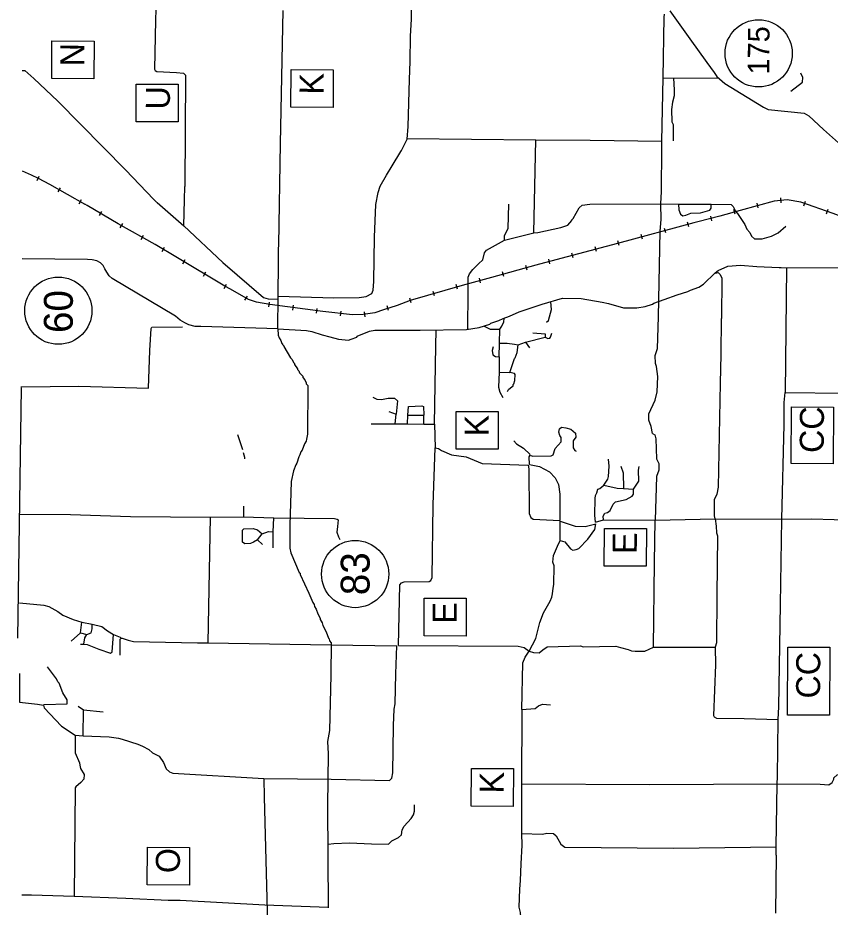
# Model space of a CAD drawing. Extents: x 299354 to 1325680, y 96128 to 228242.
# Drawn here: x 299354 to 333137, y 121656 to 158651 of the extents above; entities that cross this region are included whole.
import ezdxf

# ---------------------------------------------------------------- set-up
doc = ezdxf.new("R2010")
doc.units = 0
for name, color, linetype in [('Level 12', 7, 'Continuous'), ('Level 13', 7, 'Continuous'), ('Level 2', 7, 'Continuous'), ('Level 3', 7, 'Continuous'), ('Level 4', 7, 'Continuous'), ('Level 57', 7, 'Continuous')]:
    doc.layers.add(name, color=color, linetype=linetype)

msp = doc.modelspace()

# ---------------------------------------------------------------- linework, layer by layer
at = {"layer": 'Level 12'}
for p, q in [((330161, 157171), (330161, 157171)), ((301041, 146467), (301041, 146467)), ((313383, 135513), (313383, 135513))]:
    msp.add_line(p, q, dxfattribs=at)
for centre in [(330161, 157171), (301041, 146467), (313383, 135513)]:
    msp.add_circle(centre, 1398, dxfattribs=at)
at = {"layer": 'Level 13'}
for p, q in [((301625, 156936), (301625, 156936)), ((311569, 155744), (311569, 155744)), ((305128, 155140), (305128, 155140)), ((318436, 141524), (318436, 141524)), ((332373, 141333), (332373, 141333)), ((324597, 136657), (324597, 136657)), ((317106, 133756), (317106, 133756)), ((332221, 131118), (332221, 131118)), ((319065, 126671), (319065, 126671)), ((305595, 123397), (305595, 123397))]:
    msp.add_line(p, q, dxfattribs=at)
for points in [[(302519, 156115), (300769, 156122), (300775, 157692), (302525, 157685)], [(312463, 154922), (310713, 154930), (310720, 156499), (312470, 156492)], [(306022, 154319), (304272, 154326), (304278, 155896), (306028, 155889)], [(333265, 140102), (331515, 140109), (331525, 142464), (333275, 142457)], [(319330, 140702), (317580, 140709), (317586, 142279), (319336, 142272)], [(325491, 135835), (323741, 135842), (323747, 137412), (325497, 137405)], [(318000, 132935), (316250, 132942), (316256, 134512), (318006, 134505)], [(333113, 129642), (331363, 129649), (331374, 132475), (333124, 132468)], [(319959, 125850), (318209, 125857), (318215, 127427), (319965, 127420)], [(306489, 122575), (304739, 122582), (304746, 124152), (306496, 124145)]]:
    msp.add_lwpolyline(points, close=True, dxfattribs=at)
at = {"layer": 'Level 2'}
for points in [[(310170, 145708), (310183, 147075), (312501, 147004), (313552, 147011), (313844, 147058), (314079, 147189), (314130, 147322), (314158, 147680), (314192, 149530), (314238, 150880), (314343, 151387), (314428, 151645), (314683, 152101), (314928, 152498), (315276, 153095), (315309, 153128), (315411, 153327), (315547, 153609), (315586, 154134), (315637, 156084), (315677, 156833), (315687, 157883), (315727, 158591), (315765, 160908)], [(305089, 158996), (305085, 158554), (305033, 156521), (305065, 156454), (305132, 156421), (305949, 156380), (306249, 156344), (306331, 156268), (306305, 151635)], [(310275, 153424), (310393, 158948)], [(326463, 158936), (327303, 157778), (328003, 156788), (328308, 156377), (328423, 156210), (328754, 155915), (330363, 154934), (330562, 154832), (332054, 154685), (332253, 154567), (332856, 154003), (333485, 153447), (333932, 153043), (334287, 152715), (334725, 152269), (335006, 151967), (335073, 151862), (335107, 151815), (335153, 151743)], [(299532, 156455), (299644, 156454), (300025, 156125), (301017, 155183), (303843, 152315), (304999, 151105), (305142, 150972)], [(310203, 149208), (310275, 153424)], [(306289, 151078), (306305, 151635)], [(310201, 149032), (310203, 149208)], [(310170, 145708), (306967, 145814), (306725, 145816), (306473, 145883), (306295, 145970), (306107, 146078), (305909, 146240), (303285, 147808), (303149, 147916), (303056, 148076), (302973, 148215), (302901, 148343), (302787, 148461), (302640, 148537), (302441, 148582), (302251, 148595), (299531, 148627)], [(310170, 145708), (311354, 145639), (311579, 145604), (312011, 145466), (312336, 145380), (312693, 145285), (313102, 145248), (313219, 145280), (313453, 145370), (313470, 145403), (313981, 145615), (314206, 145663), (316083, 145663), (318018, 145679), (318544, 145774), (318987, 145911), (319021, 145944), (319364, 146058), (319532, 146140), (319799, 146237), (320210, 146425), (321163, 146733), (322000, 146984), (322775, 146977), (323658, 146819), (323924, 146767), (324548, 146586), (325098, 146581), (325449, 146645), (325742, 146742), (325809, 146783), (326236, 146929), (326780, 147124), (327223, 147262), (327324, 147328), (327675, 147441), (327868, 147573), (328348, 148043), (328482, 148142), (328876, 148314), (329402, 148359), (330093, 148303), (331010, 148269), (331094, 148269), (333771, 148244)], [(331326, 148269), (331262, 143059)], [(310170, 145708), (310185, 145449), (310217, 145333), (310299, 145223), (310332, 145106), (310365, 145090), (310364, 145056), (310414, 145006), (310414, 144972), (310701, 144511), (310767, 144444), (310816, 144310), (310866, 144268), (310866, 144235), (310989, 144050), (310989, 144017), (311038, 143967), (311071, 143883), (311203, 143740), (311202, 143690), (311285, 143589), (311351, 143472), (311350, 143422), (311416, 143355), (311398, 141338), (311362, 141130), (311345, 141047), (311277, 140931), (311175, 140665), (311124, 140591), (311089, 140474), (311039, 140392), (310953, 140126), (310910, 140051), (310825, 139802), (310720, 139361), (310670, 137553), (310662, 136587), (310710, 136394), (311061, 135583), (311094, 135549), (311094, 135499), (311462, 134713), (311625, 134336), (311674, 134252), (311690, 134169), (311756, 134052), (311837, 133859), (311927, 133675), (311927, 133625), (312009, 133491), (312041, 133374), (312172, 133114), (312270, 132847), (312303, 132813), (312319, 132738), (312385, 132654), (312372, 131304), (312318, 129013), (312230, 128555), (312259, 128030), (312239, 125880), (312267, 121630)], [(316689, 141749), (316740, 145000)], [(331131, 137801), (331217, 141734), (331225, 142651), (331262, 143059)], [(316689, 141749), (316705, 140765)], [(316705, 140765), (316855, 140731), (316971, 140646), (317394, 140467), (318002, 140395), (318659, 140106), (320576, 140039)], [(320627, 140071), (321051, 139993), (321458, 139772), (321706, 139520), (321837, 139244), (321891, 138835), (321898, 137735)], [(321907, 136910), (321914, 137718)], [(321914, 137718), (322538, 137512), (322946, 137492), (323398, 137605)], [(323382, 137671), (323708, 137769)], [(323708, 137769), (325859, 137749)], [(325859, 137749), (328353, 137810)], [(328353, 137810), (331131, 137801)], [(330970, 129469), (331008, 129994), (331064, 134252), (331131, 137801)], [(331131, 137801), (332373, 137807)], [(332373, 137807), (333299, 137782), (336317, 137721)], [(320622, 132313), (320902, 132835), (321058, 133492), (321212, 133899), (321491, 134388), (321560, 134555), (321594, 134688), (321613, 134929), (321648, 135079), (321655, 135854), (321607, 136012), (321626, 136279), (321796, 136669), (321907, 136910)], [(312365, 132572), (315119, 132529)], [(315186, 132546), (320165, 132517), (320406, 132465), (320622, 132313)], [(320316, 129874), (320350, 131824), (320452, 132056), (320622, 132313)], [(320316, 129874), (320304, 126791)], [(330929, 126795), (330948, 127086), (330970, 129469)], [(320304, 126791), (320301, 124724)], [(330888, 124170), (330929, 126795)], [(320301, 124724), (320314, 124232), (320273, 123458), (320250, 122774), (320213, 122408), (320190, 121658), (320238, 121441), (320268, 121083), (320316, 120899), (320310, 120199)], [(330885, 123820), (330888, 124170)], [(330885, 123820), (330862, 121406)], [(299516, 122170), (299920, 122167), (301696, 122117)], [(301696, 122117), (303847, 122031)], [(303847, 122031), (305614, 121949)], [(305614, 121949), (306106, 121944), (309624, 121754)], [(309624, 121754), (312267, 121663)]]:
    msp.add_lwpolyline(points, dxfattribs=at)
at = {"layer": 'Level 3'}
for points in [[(305145, 150969), (306257, 150002)], [(306257, 150002), (306289, 151078)], [(306257, 150002), (307886, 148479), (309570, 147018), (309764, 146962), (310183, 146947)], [(310195, 148408), (310201, 149032)], [(310190, 147899), (310195, 148408)], [(310183, 147075), (310188, 147666)], [(310188, 147666), (310190, 147899)], [(316740, 145003), (316750, 145657)]]:
    msp.add_lwpolyline(points, dxfattribs=at)
at = {"layer": 'Level 4'}
for p, q in [((300164, 151885), (300249, 152066)), ((301034, 151408), (301132, 151582)), ((301906, 150917), (302004, 151091)), ((331105, 150958), (331086, 151157)), ((332042, 150829), (332108, 151018)), ((302752, 150422), (302852, 150595)), ((329186, 150479), (329130, 150672)), ((330148, 150746), (330096, 150939)), ((332986, 150499), (333052, 150688)), ((328219, 150212), (328170, 150406)), ((303618, 149921), (303716, 150095)), ((326297, 149700), (326245, 149893)), ((327262, 149960), (327210, 150153)), ((304490, 149430), (304588, 149604)), ((325331, 149440), (325279, 149633)), ((305355, 148933), (305457, 149105)), ((323416, 148928), (323365, 149121)), ((324365, 149180), (324313, 149374)), ((322450, 148671), (322398, 148864)), ((306214, 148422), (306317, 148594)), ((321483, 148414), (321432, 148608)), ((307071, 147908), (307174, 148079)), ((319564, 147889), (319511, 148082)), ((320529, 148154), (320475, 148347)), ((318599, 147625), (318547, 147818)), ((307931, 147393), (308027, 147568)), ((316677, 147081), (316621, 147273)), ((317637, 147360), (317581, 147552)), ((308801, 146904), (308900, 147078)), ((315717, 146801), (315661, 146993)), ((309790, 146627), (309827, 146823)), ((310787, 146495), (310813, 146693)), ((311778, 146366), (311804, 146564)), ((314775, 146474), (314715, 146664)), ((312774, 146251), (312796, 146450)), ((313796, 146219), (313766, 146417)), ((299354, 132852), (299513, 143253))]:
    msp.add_line(p, q, dxfattribs=at)
for points in [[(326196, 156147), (326228, 158680), (326245, 158804)], [(326138, 153514), (326196, 156147)], [(326196, 156147), (326621, 156143)], [(326621, 156143), (326650, 155651), (326648, 155409), (326579, 155143), (326542, 154835), (326554, 154327), (326603, 154209), (326614, 153534)], [(326621, 156143), (328473, 156159)], [(315548, 153634), (320901, 153569)], [(320815, 149703), (320901, 153569)], [(320901, 153569), (323161, 153566), (326138, 153514)], [(326097, 150906), (326119, 151430), (326136, 153235)], [(326136, 153235), (326138, 153514)], [(302156, 150891), (300685, 151719), (300212, 151973), (299921, 152109), (299550, 152268)], [(333266, 150507), (331919, 150978), (331353, 151083), (330811, 151030), (329389, 150642), (328553, 150400), (327633, 150167), (327638, 150168), (327466, 150118), (324289, 149264), (324298, 149266), (321045, 148401), (321050, 148402), (320903, 148361), (319055, 147853), (317835, 147522), (315669, 146892), (315125, 146688), (314556, 146510), (314196, 146380), (313720, 146309), (313278, 146296), (312037, 146433), (309838, 146719), (309280, 146824), (308947, 146936), (308201, 147359), (307967, 147487), (307968, 147486), (305994, 148671), (305065, 149221), (303530, 150085), (302236, 150838), (302149, 150896), (302156, 150891), (300685, 151719), (300212, 151973), (299921, 152109), (299550, 152268)], [(333956, 150243), (333266, 150507), (331919, 150978), (331353, 151083), (330811, 151030), (329389, 150642), (328553, 150400), (327633, 150167)], [(305065, 149221), (303530, 150085), (302236, 150838), (302149, 150896)], [(319595, 149406), (319597, 149598), (319750, 149880), (319776, 150896)], [(320815, 149703), (320974, 149719), (321935, 149935), (322228, 150032), (322396, 150214), (322397, 150247), (322447, 150297), (322693, 150753), (322828, 150852), (323137, 150899), (326097, 150906)], [(326004, 146215), (326070, 149772), (326108, 150264), (326097, 150906)], [(326097, 150906), (326831, 150899)], [(326831, 150899), (326846, 150665), (326911, 150482), (327010, 150414), (327127, 150446), (327337, 150528), (327745, 150541), (328130, 150654), (328181, 150737), (328182, 150895)], [(326831, 150899), (328182, 150895)], [(328182, 150895), (329016, 150879), (329099, 150795), (329197, 150611), (329280, 150510), (329584, 150049), (329666, 149865), (329798, 149722), (329871, 149571), (329987, 149454), (330312, 149451), (330697, 149564), (330974, 149711), (331293, 149987)], [(327638, 150168), (327466, 150118), (324289, 149264)], [(319595, 149406), (320815, 149703)], [(307968, 147486), (305994, 148671), (305065, 149221)], [(318083, 147286), (318088, 147861), (318139, 148003), (318274, 148185), (318519, 148424), (318687, 148589), (318756, 148872), (318849, 148979), (319595, 149406)], [(324298, 149266), (321045, 148401)], [(321050, 148402), (320903, 148361), (319055, 147853), (317835, 147522)], [(328364, 148043), (328381, 148026), (328481, 148059), (328547, 147992), (328629, 147841), (328614, 146141)], [(314556, 146510), (314196, 146380), (313720, 146309), (313278, 146296), (312037, 146433), (309838, 146719), (309280, 146824), (308947, 146936), (308201, 147359), (307967, 147487)], [(317835, 147522), (315669, 146892), (315125, 146688), (314556, 146510)], [(318068, 145678), (318083, 147286)], [(321340, 145990), (321424, 146056), (321553, 146513), (321523, 146839)], [(319394, 145699), (319479, 145824), (319564, 146006), (319582, 146139)], [(325742, 141359), (325695, 141651), (325597, 141918), (325600, 142177), (325855, 142749), (325942, 143098), (325964, 143732), (325918, 144149), (325869, 144274), (325856, 144608), (325959, 144898), (326004, 146215)], [(328600, 144641), (328614, 146141)], [(304793, 143240), (304841, 144814), (304900, 145731), (304933, 145780), (306201, 145802)], [(318745, 145830), (319002, 145703), (319394, 145699)], [(319389, 145124), (319394, 145699)], [(320777, 145554), (321285, 145499), (321284, 145366)], [(321284, 145366), (321400, 145315), (321476, 145331), (321509, 145364), (321561, 145530)], [(319367, 144550), (319389, 145124)], [(319389, 145124), (319706, 145122), (320014, 145069), (320164, 145051)], [(319811, 143904), (319974, 144361), (320008, 144477), (320042, 144510), (320127, 144734), (320164, 145051)], [(320164, 145051), (320473, 145165)], [(320473, 145165), (321284, 145366)], [(320473, 145165), (320638, 144930)], [(319129, 144960), (319077, 144811), (319109, 144635), (319225, 144568), (319367, 144550)], [(319367, 144550), (319378, 143908)], [(328353, 137810), (328321, 137935), (328328, 138627), (328430, 138842), (328499, 139134), (328572, 143450), (328600, 144641)], [(319378, 143908), (319338, 143283), (319403, 143074), (319518, 142857)], [(319378, 143908), (319811, 143904)], [(319720, 143105), (319755, 143196), (319847, 143262), (319948, 143344), (319948, 143394), (319982, 143427), (320017, 143560), (320036, 143819), (320003, 143852), (319811, 143904)], [(299479, 143305), (299506, 143304)], [(299506, 143304), (301892, 143324), (304793, 143240)], [(314114, 142872), (314280, 142787), (314480, 142769), (314756, 142833), (315023, 142831), (315138, 142713), (315083, 142163)], [(331262, 143059), (333739, 143036)], [(315575, 142126), (315595, 142484), (316154, 142512), (316229, 142478), (316242, 142120)], [(314784, 142274), (315083, 142163)], [(315046, 141764), (315083, 142163)], [(315555, 141759), (315575, 142126)], [(315575, 142126), (316242, 142120)], [(316239, 141753), (316242, 142120)], [(314044, 141763), (315046, 141764)], [(315046, 141764), (315555, 141759)], [(315555, 141759), (316239, 141753)], [(316239, 141753), (316689, 141749)], [(320663, 140454), (320763, 140420), (321531, 140430), (321614, 140479), (321700, 140737), (321945, 141018), (321946, 141193), (321897, 141277), (321857, 141410), (321875, 141560), (321967, 141618), (322150, 141599), (322350, 141539), (322540, 141371), (322555, 141204), (322454, 141055), (322451, 140763), (322517, 140646), (322567, 140629)], [(325742, 141359), (325842, 141308), (325891, 141141), (325916, 140307), (326014, 140106), (326012, 139831), (325909, 139565), (325859, 137749)], [(308487, 141315), (308584, 141022)], [(308584, 141022), (308698, 140688)], [(319977, 141052), (320092, 140935), (320383, 140749), (320664, 140488)], [(299437, 140631), (299482, 140630)], [(315186, 132546), (315243, 135070), (315310, 135153), (315427, 135185), (316462, 135209), (316529, 135242), (316580, 135375), (316625, 138391), (316705, 140765)], [(308730, 140563), (308778, 140379), (308777, 140306)], [(320627, 140071), (320613, 140388), (320663, 140454)], [(323721, 139210), (323890, 139459), (323924, 139567), (323945, 140008), (323914, 140292)], [(320576, 140039), (320608, 139897), (320624, 138038), (320690, 137863), (320789, 137795), (321898, 137735)], [(324437, 140004), (324526, 139728), (324537, 139069)], [(324954, 139049), (325182, 139380), (325170, 139839), (325188, 139989)], [(323469, 139046), (323553, 139078), (323721, 139210)], [(323721, 139210), (324279, 139088), (324537, 139069)], [(323382, 137671), (323351, 137963), (323357, 138655), (323375, 138788), (323426, 138888), (323469, 139046)], [(323708, 137769), (323692, 137927), (323760, 138043), (323877, 138075), (323987, 138158), (324106, 138423), (324207, 138514), (324650, 138610), (324901, 138758), (324952, 138841), (324954, 139049)], [(324537, 139069), (324954, 139049)], [(299423, 138005), (299449, 138005)], [(299449, 138005), (301542, 137986), (304044, 137913), (307371, 137883)], [(308746, 138334), (308739, 137887)], [(307273, 132650), (307371, 137883)], [(307371, 137883), (308739, 137887)], [(308739, 137887), (309998, 137859)], [(309976, 137268), (309998, 137859)], [(309998, 137859), (312524, 137820), (312641, 137802), (312674, 137768), (312655, 137494), (312619, 137261), (312684, 137060), (312750, 136951)], [(325794, 132466), (325826, 135991), (325859, 137749)], [(328353, 137810), (328401, 137509), (328415, 137234), (328447, 137101), (328424, 134626), (328406, 132659), (328354, 132476)], [(309322, 136932), (309154, 136834), (309037, 136785), (308795, 136770), (308696, 136838), (308700, 137346), (308751, 137396), (309143, 137409), (309326, 137357), (309516, 137189)], [(309516, 137189), (309784, 137286), (309976, 137268)], [(309970, 136610), (309976, 137268)], [(321907, 136910), (322106, 136850), (322337, 136564), (322428, 136513), (322579, 136529), (322679, 136578), (323058, 136966), (323345, 137363), (323398, 137605)], [(309322, 136932), (309516, 137189)], [(309322, 136932), (309529, 136747)], [(299423, 134313), (300432, 134221), (300640, 134169), (301013, 133957), (301228, 133805), (301652, 133618), (302018, 133515)], [(301964, 133074), (302018, 133515)], [(302018, 133515), (302443, 133428)], [(302222, 133005), (302406, 133070), (302441, 133236), (302443, 133428)], [(302443, 133428), (302850, 133332), (303091, 133147), (303339, 132994)], [(301577, 132719), (301964, 133074)], [(301964, 133074), (302222, 133005)], [(302101, 132597), (302137, 132864), (302222, 133005)], [(302101, 132597), (302235, 132579), (302725, 132392), (303215, 132229), (303283, 132278), (303339, 132994)], [(303339, 132994), (303614, 132892), (303647, 132850)], [(303607, 132142), (303613, 132800), (303647, 132850)], [(303647, 132850), (303697, 132850), (303946, 132764), (304171, 132712), (306831, 132654), (307273, 132650)], [(301960, 132599), (302101, 132597)], [(307273, 132650), (312365, 132572)], [(309589, 127004), (312391, 126979), (314809, 126924), (314910, 127023), (314945, 127248), (314980, 129214), (315003, 129889), (315047, 130122), (315075, 131363), (315119, 132529)], [(320622, 132313), (320796, 132245), (321030, 132243), (321181, 132358), (321374, 132489), (322759, 132527), (322867, 132493), (324218, 132514), (324418, 132462), (324742, 132376), (324875, 132324)], [(324875, 132324), (325033, 132306), (325434, 132303), (325794, 132466)], [(325794, 132466), (326169, 132479), (326961, 132472)], [(326961, 132472), (328354, 132476)], [(328354, 132476), (328364, 131735), (328278, 129635), (328311, 129568), (328410, 129526), (329561, 129499), (330970, 129469)], [(299430, 131371), (299419, 130180), (300177, 130106), (300427, 130054)], [(300427, 130054), (300452, 130087), (301411, 130112), (301413, 130278), (301232, 130572), (301069, 130982), (301019, 131032), (300970, 131149), (300583, 131661)], [(300427, 130054), (300451, 129954), (301169, 129181), (301741, 128809)], [(301869, 130024), (302093, 129872)], [(302066, 128789), (302093, 129872)], [(302093, 129872), (302901, 129782)], [(320316, 129874), (320875, 129919), (321009, 130034), (321177, 130100), (321502, 130080)], [(301741, 128809), (301734, 128075), (301914, 127666), (301930, 127565), (301962, 127432), (302118, 127172), (302100, 126989), (301981, 126840), (301771, 126658), (301738, 126617), (301696, 122117)], [(301741, 128809), (302066, 128789)], [(302066, 128789), (303150, 128746), (303541, 128684), (303691, 128649)], [(303691, 128649), (304348, 128444), (304547, 128358), (304805, 128223), (304954, 128080), (305228, 127944), (305409, 127676), (305523, 127416), (305663, 127282), (305796, 127230), (309589, 127004)], [(309589, 127004), (309594, 126238)], [(330929, 126795), (332713, 126778), (333080, 126742), (333214, 126840), (333291, 126981), (333291, 127031), (333426, 127164), (333768, 127210), (333968, 127159), (334101, 127074), (334166, 126924), (334357, 126813), (334774, 126793)], [(320304, 126791), (325641, 126759), (330929, 126795)], [(309594, 126238), (309803, 118351)], [(312258, 124272), (312500, 124303), (313142, 124330), (314059, 124289), (314768, 124282), (314903, 124415), (315179, 124554), (315314, 124669), (315332, 124869), (315417, 125027), (315712, 125341), (315813, 125498), (315848, 125648), (315851, 125914)], [(320301, 124724), (321177, 124699), (321352, 124731), (321636, 124729), (321743, 124628), (321940, 124284), (322106, 124149), (326617, 124108)], [(326617, 124108), (330888, 124170)]]:
    msp.add_lwpolyline(points, dxfattribs=at)
at = {"layer": 'Level 57'}
msp.add_lwpolyline([(331501, 155606), (331983, 155969), (332001, 156161), (331911, 156345)], dxfattribs=at)

# ---------------------------------------------------------------- texts
at = {"layer": 'Level 12'}
for s, height, p in [('175', 900, (330608, 156290)), ('60', 1200, (301638, 145538)), ('83', 1200, (313980, 134632))]:
    msp.add_text(s, height=height, rotation=89.767, dxfattribs=at).set_placement(p)
at = {"layer": 'Level 13'}
for s, p in [('N', (302124, 156627)), ('K', (312068, 155459)), ('U', (305678, 154835)), ('CC', (332870, 140551)), ('K', (318935, 141238)), ('E', (325095, 136352)), ('E', (317605, 133451)), ('CC', (332718, 130336)), ('K', (319564, 126386)), ('O', (306094, 123072))]:
    msp.add_text(s, height=1000, rotation=89.767, dxfattribs=at).set_placement(p)

doc.saveas('drawing.dxf')
